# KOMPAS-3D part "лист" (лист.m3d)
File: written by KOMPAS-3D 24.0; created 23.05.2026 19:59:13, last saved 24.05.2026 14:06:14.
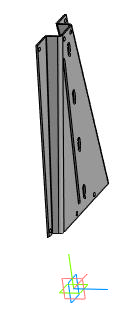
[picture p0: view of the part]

Document properties: Автор: R2D2; Полное имя файла: E:\Работа\Зайцев\GVKR1331M-1W-Fb-2P Задвижка шиберная с выдвижным штоком DN.ru Ду50-300 Ру16-10-6 с пневмоприводом\исходные материалы\DN250\лист.m3d

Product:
- Part/product: лист
    Масса: 4.141971
    Раздел спецификации: Прочие изделия
    Примечание: D040-08800

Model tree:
1. Эскиз:6  (with: Грань.Элемент выдавливания:15, Ребро.Элемент выдавливания:15)
2. Эскиз:7  (with: Грань.Элемент выдавливания:6, Ребро.Элемент выдавливания:6, Ребро.Элемент выдавливания:12)
3. Линейчатая обечайка:1
     Расстояние 1 = 10; Толщина листового тела = 4; Коэффициент = 0.5
4. Сгиб(1) - Линейчатая обечайка:1
     Радиус сгиба = 5; Коэффициент = 0.5; Величина сгиба = 5
5. Сгиб(2) - Линейчатая обечайка:1
     Радиус сгиба = 5; Коэффициент = 0.5; Величина сгиба = 5
6. Сгиб(3) - Линейчатая обечайка:1
     Радиус сгиба = 5; Коэффициент = 0.5; Величина сгиба = 5
7. Сгиб(4) - Линейчатая обечайка:1
     Радиус сгиба = 5; Коэффициент = 0.5; Величина сгиба = 5; Зазор = 1; Угол = 360; Параметр U, % = 100; Длина = 149
8. Эскиз:8  (with: Грань.Линейчатая обечайка:1, Ребро.Линейчатая обечайка:1)
9. Отверстие в листовом теле:1  (with: Грань.Линейчатая обечайка:1, Ребро.Линейчатая обечайка:1)
     Глубина выреза = 10; Расстояние 1 = 10.1296; Расстояние 2 = 10.1389
10. Отверстие в листовом теле:2  (with: Грань.Линейчатая обечайка:1, Ребро.Линейчатая обечайка:1)
     Глубина выреза = 10; Расстояние 1 = -80; Расстояние 2 = 10
11. Отверстие в листовом теле:3  (with: Грань.Линейчатая обечайка:1, Ребро.Линейчатая обечайка:1)
     Глубина выреза = 10; Расстояние 1 = -186.605; Расстояние 2 = 10
12. Отверстие в листовом теле:4  (with: Грань.Линейчатая обечайка:1, Ребро.Линейчатая обечайка:1)
     Глубина выреза = 10; Расстояние 1 = -9.00389; Расстояние 2 = 10.1389
13. Отверстие в листовом теле:5  (with: Грань.Линейчатая обечайка:1, Ребро.Линейчатая обечайка:1)
     Глубина выреза = 10; Расстояние 1 = 10.1903; Расстояние 2 = 424.727
14. Отверстие в листовом теле:6  (with: Грань.Линейчатая обечайка:1, Ребро.Линейчатая обечайка:1)
     Глубина выреза = 10; Расстояние 1 = -10; Расстояние 2 = 424.757
15. Отверстие в листовом теле:7  (with: Грань.Линейчатая обечайка:1, Ребро.Линейчатая обечайка:1)
     Глубина выреза = 10; Расстояние 1 = -49.0329; Расстояние 2 = 424.757
16. Отверстие в листовом теле:8  (with: Грань.Линейчатая обечайка:1, Ребро.Линейчатая обечайка:1)
     Глубина выреза = 10; Расстояние 1 = -39.7239; Расстояние 2 = 424.727
17. Эскиз:9  (with: Грань.Линейчатая обечайка:1, Ребро.Линейчатая обечайка:1)
18. Эскиз:10  (with: Грань.Линейчатая обечайка:1, Ребро.Линейчатая обечайка:1)
19. Вырез в листовом теле:1
     Глубина выреза = 10
20. Вырез в листовом теле:2
     Глубина выреза = 10

Expressions: 2*h
Referenced files in E:\Работа\Зайцев\GVKR1331M-1W-Fb-2P Задвижка шиберная с выдвижным штоком DN.ru Ду50-300 Ру16-10-6 с пневмоприводом\исходные материалы\DN250\: GVKR1331M-1W-Fb-2P Задвижка шиберная с выдвижным штоком DN.ru Ду250 Ру10.a3d
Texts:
  Шаг 2
  Шаг 1
  Затвор дисковый DN.ru Ду Ру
